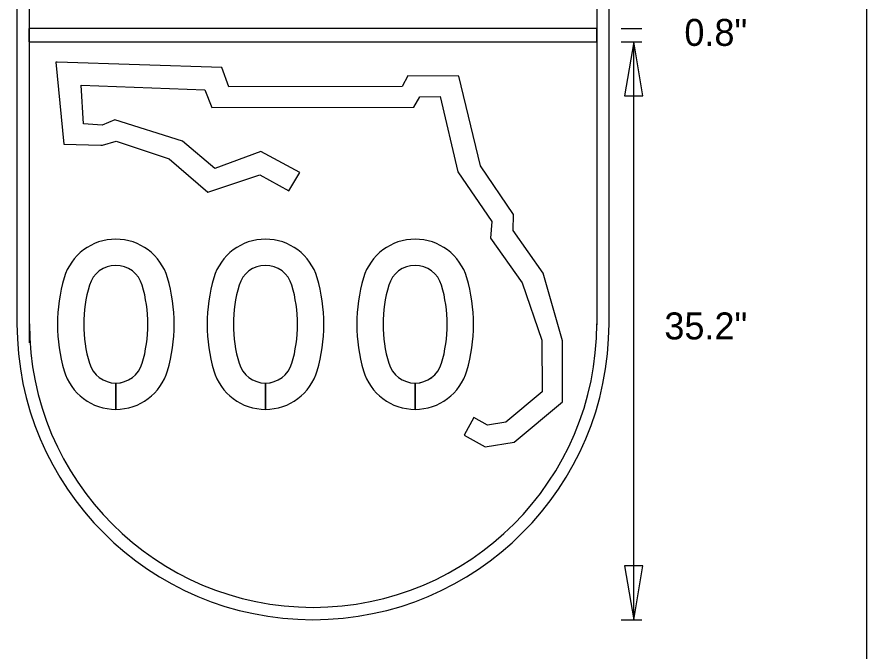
# Model space of a CAD drawing. Extents: x 0 to 770, y 0 to 495.
# Drawn here: x 467.1 to 577.5, y 207.3 to 289.7 of the extents above; entities that cross this region are included whole.
import ezdxf

# ---------------------------------------------------------------- set-up
doc = ezdxf.new("R2010")
doc.units = 0
for name, color, linetype in [('Core', 7, 'Continuous'), ('Default', 7, 'Continuous'), ('Dimension', 7, 'Continuous'), ('GSBWFill', 7, 'Continuous'), ('GSDims', 7, 'Continuous'), ('IndexDetail_0', 7, 'Continuous'), ('SheetLines_dp', 7, 'Continuous'), ('TextStructures', 7, 'Continuous'), ('XSCell', 7, 'Continuous')]:
    doc.layers.add(name, color=color, linetype=linetype)

msp = doc.modelspace()

# ---------------------------------------------------------------- linework, layer by layer
at = {"layer": 'Core'}
for p, q in [((479.93, 242.15), (479.93, 238.73)), ((479.93, 238.73), (479.93, 242.15)), ((499.37, 242.15), (499.37, 238.73)), ((499.37, 238.73), (499.37, 242.15)), ((518.81, 242.15), (518.81, 238.73)), ((518.81, 238.73), (518.81, 242.15))]:
    msp.add_line(p, q, dxfattribs=at)
for centre, radius, start, end in [((479.93, 253.84), 7, 16.4025, 163.5975), ((499.37, 253.84), 7, 16.4025, 163.5975), ((518.81, 253.84), 7, 16.4025, 163.5975), ((479.93, 253.84), 3.58, 16.4025, 163.5975), ((499.37, 253.84), 3.58, 16.4025, 163.5975), ((518.81, 253.84), 3.58, 16.4025, 163.5975), ((493.71, 249.78), 21.36, 163.5975, 196.4025), ((466.15, 249.78), 21.36, 343.5975, 16.4025), ((513.15, 249.78), 21.36, 163.5975, 196.4025), ((485.59, 249.78), 21.36, 343.5975, 16.4025), ((532.59, 249.78), 21.36, 163.5975, 196.4025), ((505.03, 249.78), 21.36, 343.5975, 16.4025), ((493.71, 249.78), 17.94, 163.5975, 196.4025), ((466.15, 249.78), 17.94, 343.5975, 16.4025), ((513.15, 249.78), 17.94, 163.5975, 196.4025), ((485.59, 249.78), 17.94, 343.5975, 16.4025), ((532.59, 249.78), 17.94, 163.5975, 196.4025), ((505.03, 249.78), 17.94, 343.5975, 16.4025), ((479.93, 245.73), 3.58, 196.4025, 270), ((479.93, 245.73), 3.58, 270.0171, 343.5975), ((499.37, 245.73), 3.58, 196.4025, 270), ((499.37, 245.73), 3.58, 270.0171, 343.5975), ((518.81, 245.73), 3.58, 196.4025, 270), ((518.81, 245.73), 3.58, 270.0171, 343.5975), ((479.93, 245.73), 7, 196.4025, 270), ((479.93, 245.73), 7, 270.0087, 343.5975), ((499.37, 245.73), 7, 196.4025, 270), ((499.37, 245.73), 7, 270.0087, 343.5975), ((518.81, 245.73), 7, 196.4025, 270), ((518.81, 245.73), 7, 270.0087, 343.5975)]:
    msp.add_arc(centre, radius, start, end, dxfattribs=at)
at = {"layer": 'Default'}
for points in [[(472.32, 283.82), (472.13, 283.82)], [(472.13, 283.82), (473.18, 273.2), (477.97, 273.06)], [(525.17, 235.39), (527.9, 233.88), (531.69, 234.46), (537.93, 239.72), (537.97, 247.64), (535.45, 256.43), (531.52, 261.98), (531.6, 264.05), (527.31, 270.35), (524.47, 282.03), (517.88, 282.08), (517.11, 280.68), (494.59, 280.65), (493.72, 283.14), (472.32, 283.82)], [(478.2, 273.06), (479.99, 273.58), (486.86, 271.29), (491.87, 266.96), (498.64, 269.22), (502.4, 267.14), (503.83, 269.52), (498.77, 272.21), (492.78, 270.04), (488.61, 273.56), (479.82, 276.35), (478.15, 275.67), (475.75, 275.82), (475.44, 280.84), (491.51, 280.26), (492.39, 277.94), (518.64, 278.01)], [(518.64, 278.01), (519.42, 279.35), (522.06, 279.39), (524.37, 269.58), (528.76, 263.14), (528.61, 260.99), (532.72, 255.17), (535.25, 247.72)], [(477.97, 273.06), (478.2, 273.06)], [(535.25, 247.72), (535.29, 241.02)], [(535.29, 241.02), (530.58, 237.05), (528.21, 236.66), (526.43, 237.69), (525.17, 235.39)]]:
    msp.add_lwpolyline(points, dxfattribs=at)
at = {"layer": 'Dimension'}
for points in [[(547.2, 286.49), (546.01, 279.48), (548.39, 279.48)], [(547.2, 211.41), (548.39, 218.42), (546.01, 218.42)]]:
    msp.add_lwpolyline(points, close=True, dxfattribs=at)
for centre, radius, start, end in [((479.93, 253.84), 7, 16.4025, 163.5975), ((499.37, 253.84), 7, 16.4025, 163.5975), ((518.81, 253.84), 7, 16.4025, 163.5975), ((479.93, 253.84), 3.58, 16.4025, 163.5975), ((499.37, 253.84), 3.58, 16.4025, 163.5975), ((518.81, 253.84), 3.58, 16.4025, 163.5975), ((493.71, 249.78), 21.36, 163.5975, 196.4025), ((466.15, 249.78), 21.36, 343.5975, 16.4025), ((513.15, 249.78), 21.36, 163.5975, 196.4025), ((485.59, 249.78), 21.36, 343.5975, 16.4025), ((532.59, 249.78), 21.36, 163.5975, 196.4025), ((505.03, 249.78), 21.36, 343.5975, 16.4025), ((493.71, 249.78), 17.94, 163.5975, 196.4025), ((466.15, 249.78), 17.94, 343.5975, 16.4025), ((513.15, 249.78), 17.94, 163.5975, 196.4025), ((485.59, 249.78), 17.94, 343.5975, 16.4025), ((532.59, 249.78), 17.94, 163.5975, 196.4025), ((505.03, 249.78), 17.94, 343.5975, 16.4025), ((479.93, 245.73), 3.58, 196.4025, 343.5975), ((499.37, 245.73), 3.58, 196.4025, 343.5975), ((518.81, 245.73), 3.58, 196.4025, 343.5975), ((479.93, 245.73), 7, 196.4025, 343.5975), ((499.37, 245.73), 7, 196.4025, 343.5975), ((518.81, 245.73), 7, 196.4025, 343.5975)]:
    msp.add_arc(centre, radius, start, end, dxfattribs=at)
at = {"layer": 'GSBWFill'}
for p, q in [((467.09, 302.19), (467.09, 249.86)), ((468.7, 247.37), (468.7, 302.19)), ((542.39, 302.19), (542.39, 249.73)), ((543.99, 249.86), (543.99, 302.19)), ((542.41, 288.2), (468.61, 288.2)), ((468.61, 286.49), (542.41, 286.49))]:
    msp.add_line(p, q, dxfattribs=at)
for points in [[(468.61, 288.2), (468.61, 286.49)], [(542.41, 286.49), (542.41, 288.2)]]:
    msp.add_lwpolyline(points, dxfattribs=at)
at = {"layer": 'GSDims'}
for p, q in [((545.59, 288.2), (548.26, 288.2)), ((545.59, 288.2), (548.26, 288.2)), ((545.59, 286.49), (548.26, 286.49)), ((545.59, 286.49), (548.26, 286.49)), ((547.2, 211.41), (547.2, 286.49)), ((545.59, 211.41), (548.26, 211.41))]:
    msp.add_line(p, q, dxfattribs=at)
at = {"layer": 'IndexDetail_0'}
for centre, radius, end in [((505.54, 249.86), 38.45, 360), ((505.55, 249.86), 36.85, 0)]:
    msp.add_arc(centre, radius, 180, end, dxfattribs=at)
at = {"layer": 'SheetLines_dp'}
msp.add_line((577.5, 0), (577.5, 495), dxfattribs=at)
at = {"layer": 'XSCell'}
for p, q in [((479.93, 242.15), (479.93, 238.73)), ((479.93, 238.73), (479.93, 242.15)), ((499.37, 242.15), (499.37, 238.73)), ((499.37, 238.73), (499.37, 242.15)), ((518.81, 242.15), (518.81, 238.73)), ((518.81, 238.73), (518.81, 242.15))]:
    msp.add_line(p, q, dxfattribs=at)
for centre, radius, start, end in [((479.93, 253.84), 7, 16.4025, 163.5975), ((499.37, 253.84), 7, 16.4025, 163.5975), ((518.81, 253.84), 7, 16.4025, 163.5975), ((479.93, 253.84), 3.58, 16.4025, 163.5975), ((499.37, 253.84), 3.58, 16.4025, 163.5975), ((518.81, 253.84), 3.58, 16.4025, 163.5975), ((493.71, 249.78), 21.36, 163.5975, 196.4025), ((466.15, 249.78), 21.36, 343.5975, 16.4025), ((513.15, 249.78), 21.36, 163.5975, 196.4025), ((485.59, 249.78), 21.36, 343.5975, 16.4025), ((532.59, 249.78), 21.36, 163.5975, 196.4025), ((505.03, 249.78), 21.36, 343.5975, 16.4025), ((493.71, 249.78), 17.94, 163.5975, 196.4025), ((466.15, 249.78), 17.94, 343.5975, 16.4025), ((513.15, 249.78), 17.94, 163.5975, 196.4025), ((485.59, 249.78), 17.94, 343.5975, 16.4025), ((532.59, 249.78), 17.94, 163.5975, 196.4025), ((505.03, 249.78), 17.94, 343.5975, 16.4025), ((479.93, 245.73), 3.58, 196.4025, 270), ((479.93, 245.73), 3.58, 270.0171, 343.5975), ((499.37, 245.73), 3.58, 196.4025, 270), ((499.37, 245.73), 3.58, 270.0171, 343.5975), ((518.81, 245.73), 3.58, 196.4025, 270), ((518.81, 245.73), 3.58, 270.0171, 343.5975), ((479.93, 245.73), 7, 196.4025, 270), ((479.93, 245.73), 7, 270.0087, 343.5975), ((499.37, 245.73), 7, 196.4025, 270), ((499.37, 245.73), 7, 270.0087, 343.5975), ((518.81, 245.73), 7, 196.4025, 270), ((518.81, 245.73), 7, 270.0087, 343.5975)]:
    msp.add_arc(centre, radius, start, end, dxfattribs=at)

# ---------------------------------------------------------------- texts
at = {"layer": 'TextStructures'}
for s, p in [('0.8"', (553.78, 285.95)), ('35.2"', (551.18, 247.82))]:
    msp.add_text(s, height=3.5, dxfattribs=at).set_placement(p)

doc.saveas('drawing.dxf')
